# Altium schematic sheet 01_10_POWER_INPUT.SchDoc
size 289 x 396 mm
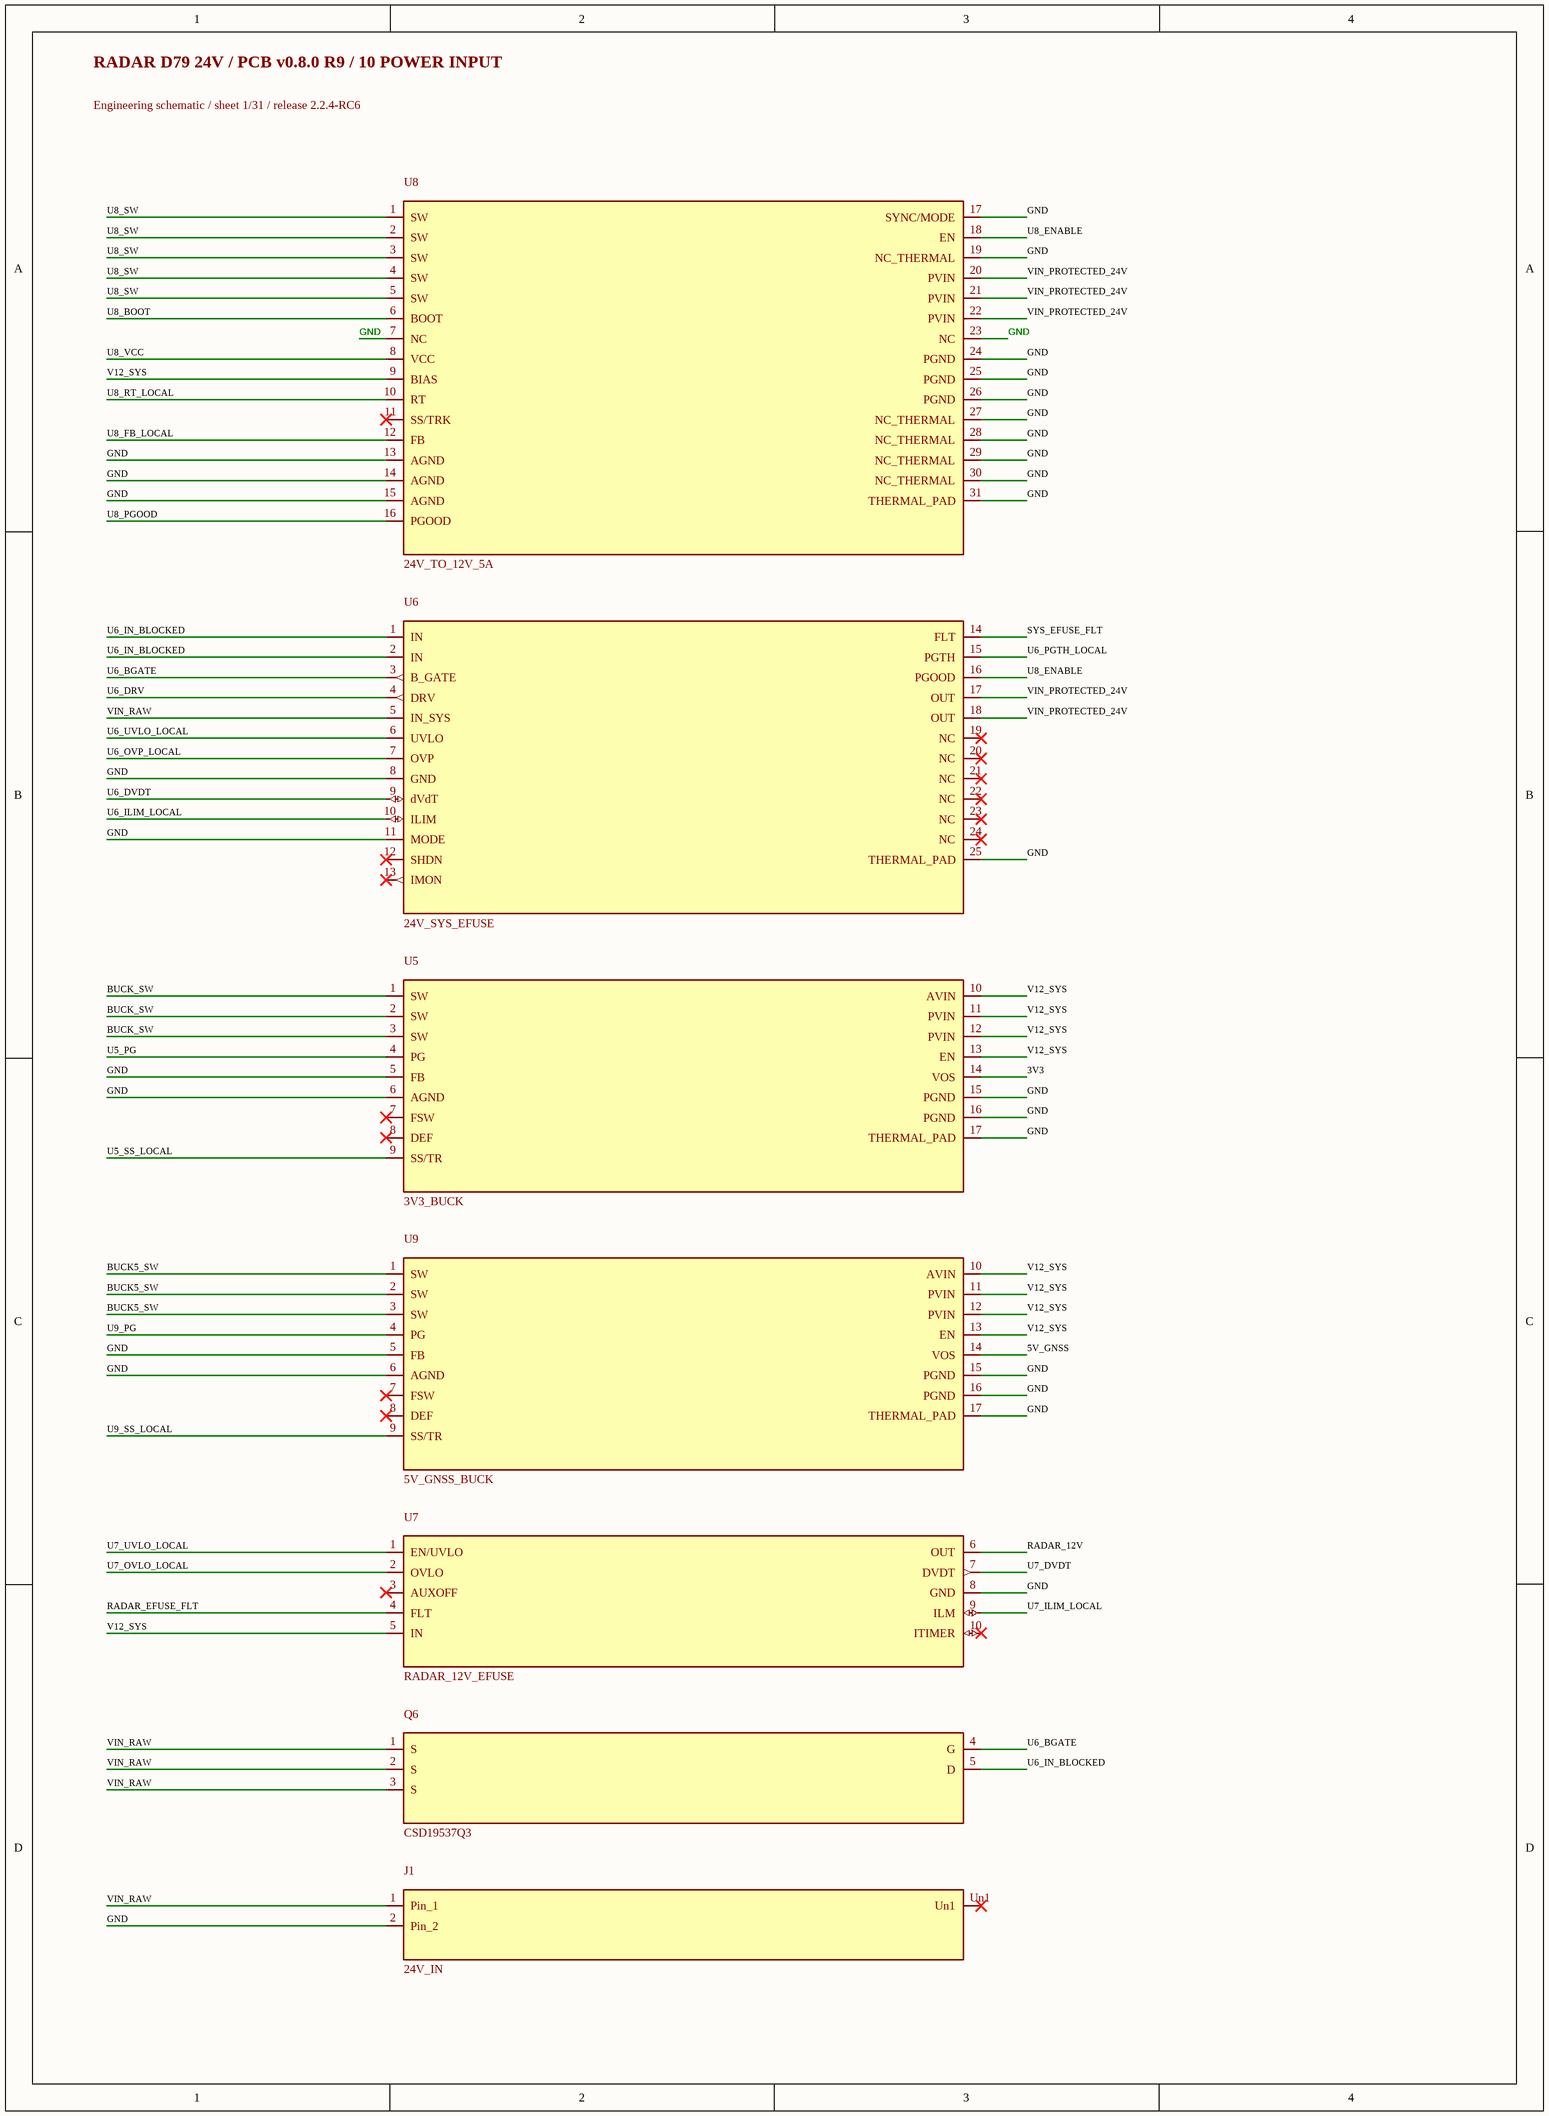
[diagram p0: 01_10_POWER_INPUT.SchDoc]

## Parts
J1  24V_IN  [Molex_43650-0200_RA_THT_2P]
Q6  CSD19537Q3  [VSON-8_3.3x3.3mm_P0.65mm_NexFET]
U5  3V3_BUCK  [VQFN-16-1EP_3x3mm_P0.5mm_EP1.68x1.68mm]
U6  24V_SYS_EFUSE  [Texas_RGE0024C_VQFN-24-1EP_4x4mm_P0.5mm_EP2.1x2.1mm]
U7  RADAR_12V_EFUSE  [TPS259470A_RPW0010A_VQFN-HR-10_2x2mm_P0.475mm]
U8  24V_TO_12V_5A  [Texas_RNP0030B_WQFN-30-1EP_4x6mm_P0.5mm_EP1.8x4.5mm_ThermalVias]
U9  5V_GNSS_BUCK  [VQFN-16-1EP_3x3mm_P0.5mm_EP1.68x1.68mm]

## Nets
3V3: U5.14(VOS)
5V_GNSS: U9.14(VOS)
BUCK5_SW: U9.1(SW) U9.2(SW) U9.3(SW)
BUCK_SW: U5.1(SW) U5.2(SW) U5.3(SW)
GND: J1.2(Pin_2) U5.5(FB) U5.6(AGND) U5.15(PGND) U5.16(PGND) U5.17(THERMAL_PAD) U6.8(GND) U6.11(MODE) U6.25(THERMAL_PAD) U7.8(GND) U8.7(NC) U8.13(AGND) U8.14(AGND) U8.15(AGND) U8.17(SYNC/MODE) U8.19(NC_THERMAL) U8.23(NC) U8.24(PGND) U8.25(PGND) U8.26(PGND) U8.27(NC_THERMAL) U8.28(NC_THERMAL) U8.29(NC_THERMAL) U8.30(NC_THERMAL) U8.31(THERMAL_PAD) U9.5(FB) U9.6(AGND) U9.15(PGND) U9.16(PGND) U9.17(THERMAL_PAD)
RADAR_12V: U7.6(OUT)
RADAR_EFUSE_FLT: U7.4(FLT)
SYS_EFUSE_FLT: U6.14(FLT)
U5_PG: U5.4(PG)
U5_SS_LOCAL: U5.9(SS/TR)
U6_BGATE: Q6.4(G) U6.3(B_GATE)
U6_DRV: U6.4(DRV)
U6_DVDT: U6.9(dVdT)
U6_ILIM_LOCAL: U6.10(ILIM)
U6_IN_BLOCKED: Q6.5(D) U6.1(IN) U6.2(IN)
U6_OVP_LOCAL: U6.7(OVP)
U6_PGTH_LOCAL: U6.15(PGTH)
U6_UVLO_LOCAL: U6.6(UVLO)
U7_DVDT: U7.7(DVDT)
U7_ILIM_LOCAL: U7.9(ILM)
U7_OVLO_LOCAL: U7.2(OVLO)
U7_UVLO_LOCAL: U7.1(EN/UVLO)
U8_BOOT: U8.6(BOOT)
U8_ENABLE: U6.16(PGOOD) U8.18(EN)
U8_FB_LOCAL: U8.12(FB)
U8_PGOOD: U8.16(PGOOD)
U8_RT_LOCAL: U8.10(RT)
U8_SW: U8.1(SW) U8.2(SW) U8.3(SW) U8.4(SW) U8.5(SW)
U8_VCC: U8.8(VCC)
U9_PG: U9.4(PG)
U9_SS_LOCAL: U9.9(SS/TR)
V12_SYS: U5.10(AVIN) U5.11(PVIN) U5.12(PVIN) U5.13(EN) U7.5(IN) U8.9(BIAS) U9.10(AVIN) U9.11(PVIN) U9.12(PVIN) U9.13(EN)
VIN_PROTECTED_24V: U6.17(OUT) U6.18(OUT) U8.20(PVIN) U8.21(PVIN) U8.22(PVIN)
VIN_RAW: J1.1(Pin_1) Q6.1(S) Q6.2(S) Q6.3(S) U6.5(IN_SYS)

Not connected (* = marked no-connect by the designer): J1 Un1*; U5 7(FSW)* 8(DEF)*; U6 12(SHDN)* 13(IMON)* 19(NC)* 20(NC)* 21(NC)* 22(NC)* 23(NC)* 24(NC)*; U7 3(AUXOFF)* 10(ITIMER)*; U8 11(SS/TRK)*; U9 7(FSW)* 8(DEF)*

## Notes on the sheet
- RADAR D79 24V / PCB v0.8.0 R9 / 10 POWER INPUT
- Engineering schematic / sheet 1/31 / release 2.2.4-RC6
